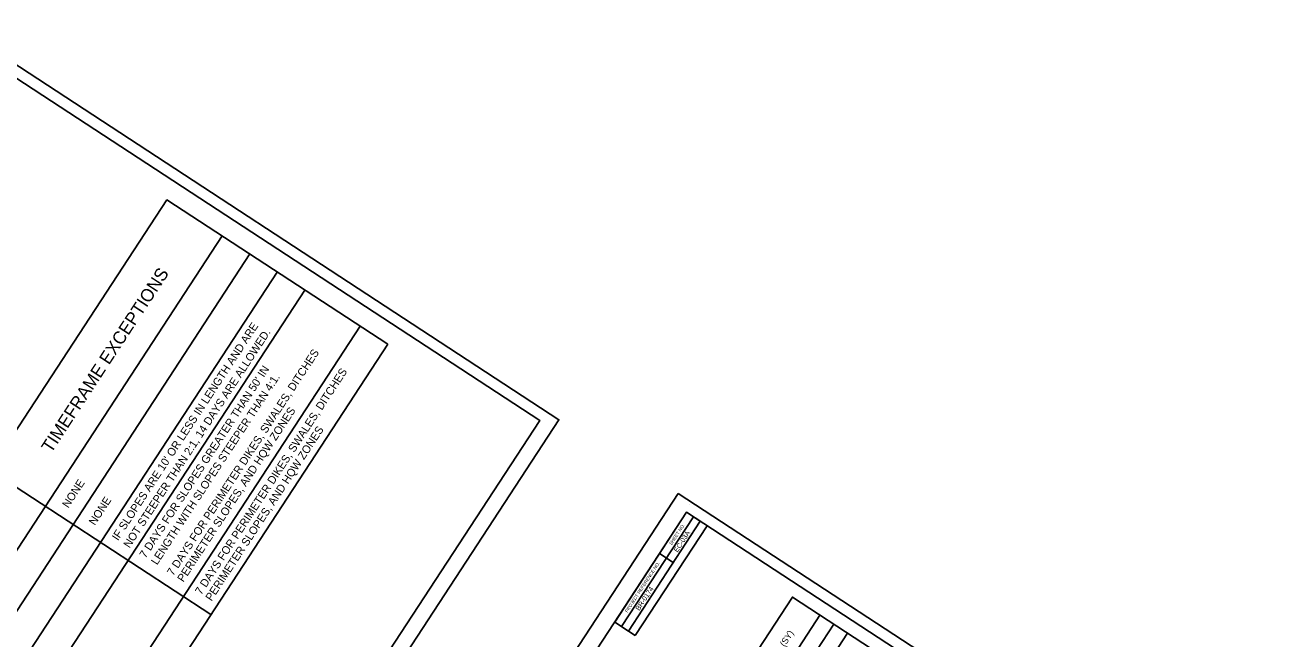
# Model space of a CAD drawing. Extents: x 1190029 to 2387899, y 163128 to 333969.
# Drawn here: x 2382621 to 2386455, y 331307 to 333180 of the extents above; entities that cross this region are included whole.
import ezdxf

# ---------------------------------------------------------------- set-up
doc = ezdxf.new("R2010")
doc.units = 0
for name, color, linetype in [('Matting Summary Sheet CELL', 7, 'Continuous'), ('Sheet_Plot_Border_Outside_CELL', 7, 'Continuous'), ('Stabilization Guidelines Sheet CELL', 7, 'Continuous')]:
    doc.layers.add(name, color=color, linetype=linetype)

msp = doc.modelspace()

# ---------------------------------------------------------------- linework, layer by layer
at = {"layer": 'Matting Summary Sheet CELL'}
for p, q in [((2384619.6, 331746.4), (2384619.6, 331746.4)), ((2384648.1, 331717), (2384648.1, 331717)), ((2384440.7, 331344.7), (2384659.6, 331679.6)), ((2384461.6, 331331), (2384680.5, 331665.9)), ((2384482.5, 331317.3), (2384701.5, 331652.2)), ((2384556.6, 331567.7), (2384598.5, 331540.4)), ((2384174.2, 330229.6), (2384961.8, 331434.4)), ((2384258.4, 330174.6), (2385046, 331379.4)), ((2384300.4, 330147.1), (2385088.1, 331351.9)), ((2384342.5, 330119.6), (2385130.1, 331324.3)), ((2384461.6, 331331), (2384482.5, 331317.3))]:
    msp.add_line(p, q, dxfattribs=at)
for points in [[(2384638.6, 331693.3), (2382997, 329182.3), (2384754.7, 328033.2), (2386396.3, 330544.2)], [(2384419.7, 331358.4), (2384638.6, 331693.3), (2384680.5, 331665.9), (2384461.6, 331331)], [(2384174.2, 330229.6), (2384961.8, 331434.4), (2386308.4, 330554), (2385520.8, 329349.3)]]:
    msp.add_lwpolyline(points, close=True, dxfattribs=at)
at = {"layer": 'Sheet_Plot_Border_Outside_CELL'}
for points in [[(2382408.3, 333179.5), (2380547.8, 330333.7), (2382389.2, 329129.9), (2384249.7, 331975.7)], [(2384613.6, 331750.3), (2382753.2, 328904.5), (2384594.6, 327700.7), (2386455.1, 330546.5)]]:
    msp.add_lwpolyline(points, close=True, dxfattribs=at)
at = {"layer": 'Stabilization Guidelines Sheet CELL'}
for p, q in [((2381646.9, 330126.9), (2383222.1, 332536.3)), ((2381731.1, 330071.9), (2383306.3, 332481.3)), ((2381815.2, 330016.9), (2383390.4, 332426.3)), ((2381899.4, 329961.9), (2383474.6, 332371.3)), ((2382067.9, 329851.7), (2383643.1, 332261.1)), ((2382152.1, 329796.6), (2383727.3, 332206)), ((2382514.4, 331821.3), (2383187.7, 331381.1))]:
    msp.add_line(p, q, dxfattribs=at)
msp.add_lwpolyline([(2382433.3, 333122.5), (2380791.8, 330611.6), (2382549.4, 329462.5), (2384190.9, 331973.4)], close=True, dxfattribs=at)
msp.add_lwpolyline([(2382152.1, 329796.6), (2381478.6, 330236.9), (2383053.8, 332646.3), (2383727.3, 332206)], dxfattribs=at)

# ---------------------------------------------------------------- texts
at = {"layer": 'Matting Summary Sheet CELL'}
for s, height, p in [('SHEET NO.', 10, (2384593.5, 331592.1)), ('EC-03A', 15, (2384611.2, 331569.9)), ('PROJECT REFERENCE NO.', 10, (2384458.5, 331386.1)), ('BR-0174', 15, (2384494.7, 331391.7)), ('ESTIMATE  (SY)', 19.525, (2384859, 331160.2))]:
    msp.add_text(s, height=height, rotation=56.8248, dxfattribs=at).set_placement(p)
at = {"layer": 'Stabilization Guidelines Sheet CELL'}
for s, height, p in [('TIMEFRAME EXCEPTIONS', 39.049, (2382700.8, 331871.5)), ("IF SLOPES ARE 10' OR LESS IN LENGTH AND ARE", 24.418, (2382904.2, 331605)), ('NOT STEEPER THAN 2:1, 14 DAYS ARE ALLOWED.', 24.418, (2382939.5, 331582.4)), ('7 DAYS FOR PERIMETER DIKES, SWALES, DITCHES', 24.418, (2383072.4, 331497.5)), ("7 DAYS FOR SLOPES GREATER THAN 50' IN", 24.418, (2382988.3, 331551.2)), ('LENGTH WITH SLOPES STEEPER THAN 4:1.', 24.418, (2383023.5, 331530.8)), ('7 DAYS FOR PERIMETER DIKES, SWALES, DITCHES', 24.418, (2383158, 331439.4)), ('PERIMETER SLOPES, AND HQW ZONES', 24.418, (2383103.7, 331478.4)), ('PERIMETER SLOPES, AND HQW ZONES', 24.418, (2383189.7, 331420.5)), ('NONE', 24.42, (2382752.6, 331704.5)), ('NONE', 24.42, (2382833.7, 331651.5))]:
    msp.add_text(s, height=height, rotation=56.8248, dxfattribs=at).set_placement(p)

doc.saveas('drawing.dxf')
